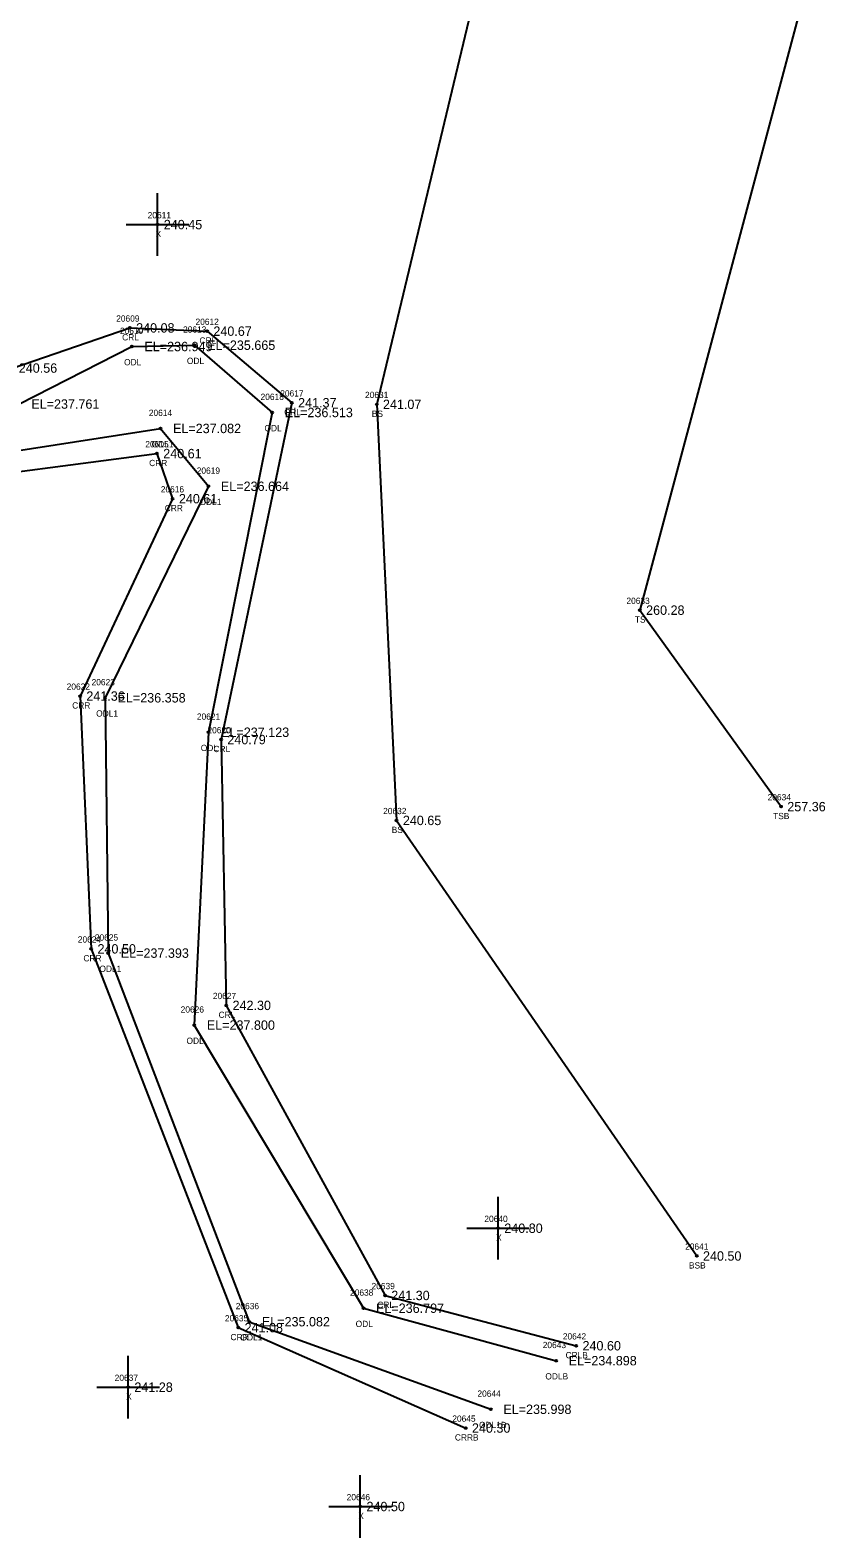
# Model space of a CAD drawing. Extents: x 2275563 to 2277161, y 1075719 to 1076412.
# Drawn here: x 2276442.5 to 2276569.6, y 1075719.3 to 1075959.9 of the extents above; entities that cross this region are included whole.
import ezdxf

# ---------------------------------------------------------------- set-up
doc = ezdxf.new("R2010")
doc.units = 0
for name, color, linetype in [('RD_DTM_BkLn2', 7, 'Continuous'), ('RD_DTM_BkLn_txCode', 7, 'Continuous'), ('RD_EX_H2O', 7, 'Continuous'), ('RD_EX_H2O_txCode', 7, 'Continuous'), ('RD_EX_Misc', 7, 'Continuous'), ('RD_EX_Misc_txCode', 7, 'Continuous'), ('RD_EX_TX_H2O_ELEV', 7, 'Continuous'), ('RD_EX_TX_Misc_ELEV', 7, 'Continuous'), ('RD_SMD_Locator', 7, 'Continuous')]:
    doc.layers.add(name, color=color, linetype=linetype)

msp = doc.modelspace()

# ---------------------------------------------------------------- linework, layer by layer
at = {"layer": 'RD_DTM_BkLn2'}
for points in [[(2276519.11, 1075988.97), (2276497.82, 1075900.18), (2276501, 1075833.77), (2276548.94, 1075764.25)], [(2276569.56, 1075978.62), (2276539.85, 1075867.33), (2276562.4, 1075835.97)]]:
    msp.add_lwpolyline(points, dxfattribs=at)
at = {"layer": 'RD_EX_H2O'}
for points in [[(2276371.99, 1076084.86), (2276373.47, 1076057.63), (2276371.02, 1076053.34), (2276370.27, 1076037.47), (2276373.78, 1076001.78), (2276377.12, 1075939.07), (2276387.12, 1075924.65), (2276409.24, 1075914.33), (2276440.66, 1075900.23), (2276458.72, 1075909.41), (2276468.75, 1075909.62), (2276481.14, 1075898.88), (2276470.97, 1075847.84), (2276468.69, 1075801.1), (2276495.71, 1075755.91), (2276526.48, 1075747.54)], [(2276337.52, 1076082.32), (2276336.19, 1076056.07), (2276339.64, 1076049.32), (2276347.49, 1076019.86), (2276346.94, 1075980.53), (2276334.04, 1075961.68), (2276358.91, 1075924.16), (2276390.72, 1075889.91), (2276404.64, 1075906.32), (2276409.35, 1075902.87), (2276425.82, 1075890.52), (2276463.29, 1075896.33), (2276470.94, 1075887.1), (2276454.43, 1075853.34), (2276454.95, 1075812.59), (2276477.48, 1075753.76), (2276516.05, 1075739.78)], [(2276374.66, 1076053.77), (2276373.09, 1076038.49), (2276378.35, 1076001.85), (2276379.41, 1075939.56), (2276393.18, 1075928.69), (2276410.52, 1075916.05), (2276439.66, 1075905.97), (2276458.4, 1075912.38), (2276470.74, 1075911.86), (2276484.27, 1075900.43), (2276472.97, 1075846.67), (2276473.8, 1075804.25), (2276499.15, 1075757.95), (2276529.69, 1075749.92)], [(2276331.39, 1075956.06), (2276351.04, 1075920.9), (2276389.88, 1075888.34), (2276407.37, 1075900.15), (2276425.36, 1075887.46), (2276462.73, 1075892.32), (2276465.23, 1075885.12), (2276450.45, 1075853.62), (2276452.23, 1075813.27), (2276475.72, 1075752.81), (2276512.04, 1075736.79)]]:
    msp.add_lwpolyline(points, dxfattribs=at)
at = {"layer": 'RD_EX_Misc'}
for p, q in [((2276462.82, 1075923.87), (2276462.82, 1075933.87)), ((2276457.82, 1075928.87), (2276467.82, 1075928.87)), ((2276517.2, 1075763.68), (2276517.2, 1075773.68)), ((2276512.2, 1075768.68), (2276522.2, 1075768.68)), ((2276458.12, 1075738.31), (2276458.12, 1075748.31)), ((2276453.12, 1075743.31), (2276463.12, 1075743.31)), ((2276495.19, 1075719.26), (2276495.19, 1075729.26)), ((2276490.19, 1075724.26), (2276500.19, 1075724.26))]:
    msp.add_line(p, q, dxfattribs=at)
at = {"layer": 'RD_SMD_Locator'}
for centre in [(2276462.82, 1075928.87), (2276458.4, 1075912.38), (2276470.74, 1075911.86), (2276458.72, 1075909.41), (2276468.75, 1075909.62), (2276484.27, 1075900.43), (2276497.82, 1075900.18), (2276481.14, 1075898.88), (2276463.29, 1075896.33), (2276462.73, 1075892.32), (2276470.94, 1075887.1), (2276465.23, 1075885.12), (2276539.85, 1075867.33), (2276450.45, 1075853.62), (2276454.43, 1075853.34), (2276470.97, 1075847.84), (2276472.97, 1075846.67), (2276562.4, 1075835.97), (2276501, 1075833.77), (2276452.23, 1075813.27), (2276454.95, 1075812.59), (2276473.8, 1075804.25), (2276468.69, 1075801.1), (2276517.2, 1075768.68), (2276548.94, 1075764.25), (2276499.15, 1075757.95), (2276495.71, 1075755.91), (2276477.48, 1075753.76), (2276475.72, 1075752.81), (2276529.69, 1075749.92), (2276526.48, 1075747.54), (2276458.12, 1075743.31), (2276516.05, 1075739.78), (2276512.04, 1075736.79), (2276495.19, 1075724.26)]:
    msp.add_circle(centre, 0.15, dxfattribs=at)

# ---------------------------------------------------------------- texts
at = {"layer": 'RD_DTM_BkLn_txCode'}
for s, p in [('20631', (2276495.96, 1075901.18)), ('BS', (2276497.04, 1075898.18)), ('20633', (2276537.71, 1075868.33)), ('TS', (2276539.06, 1075865.33)), ('20634', (2276560.26, 1075836.97)), ('20632', (2276498.85, 1075834.77)), ('TSB', (2276561.13, 1075833.97)), ('BS', (2276500.22, 1075831.77)), ('20641', (2276547.08, 1075765.25)), ('BSB', (2276547.69, 1075762.25))]:
    msp.add_text(s, height=1, dxfattribs=at).set_placement(p)
at = {"layer": 'RD_EX_H2O_txCode'}
for s, p in [('20609', (2276456.22, 1075913.38)), ('20610', (2276456.82, 1075911.41)), ('20613', (2276466.9, 1075911.62)), ('20612', (2276468.89, 1075912.86)), ('CRL', (2276457.17, 1075910.38)), ('CRL', (2276469.52, 1075909.86)), ('ODL', (2276457.48, 1075906.41)), ('ODL', (2276467.51, 1075906.62)), ('20617', (2276482.42, 1075901.43)), ('20618', (2276479.28, 1075900.88)), ('20614', (2276461.43, 1075898.33)), ('CRL', (2276483.05, 1075898.43)), ('ODL', (2276479.9, 1075895.88)), ('20615', (2276460.87, 1075893.32)), ('ODL1', (2276461.88, 1075893.33)), ('CRR', (2276461.48, 1075890.32)), ('20619', (2276469.08, 1075889.1)), ('20616', (2276463.34, 1075886.12)), ('CRR', (2276463.97, 1075883.12)), ('ODL1', (2276469.53, 1075884.1)), ('20622', (2276448.31, 1075854.62)), ('20623', (2276452.29, 1075855.34)), ('CRR', (2276449.19, 1075851.62)), ('ODL1', (2276453.02, 1075850.34)), ('20621', (2276469.11, 1075849.84)), ('20620', (2276470.79, 1075847.67)), ('ODL', (2276469.73, 1075844.84)), ('CRL', (2276471.75, 1075844.67)), ('20625', (2276452.81, 1075814.59)), ('20624', (2276450.09, 1075814.27)), ('CRR', (2276450.98, 1075811.27)), ('ODL1', (2276453.54, 1075809.59)), ('20627', (2276471.66, 1075805.25)), ('20626', (2276466.52, 1075803.1)), ('CRL', (2276472.57, 1075802.25)), ('ODL', (2276467.45, 1075798.1)), ('20638', (2276493.57, 1075757.91)), ('20639', (2276497, 1075758.95)), ('20636', (2276475.31, 1075755.76)), ('CRL', (2276497.92, 1075755.95)), ('20635', (2276473.58, 1075753.81)), ('ODL', (2276494.46, 1075752.91)), ('CRR', (2276474.47, 1075750.81)), ('ODL1', (2276476.07, 1075750.76)), ('20642', (2276527.55, 1075750.92)), ('20643', (2276524.34, 1075749.54)), ('CRLB', (2276527.99, 1075747.92)), ('ODLB', (2276524.76, 1075744.54)), ('20644', (2276513.91, 1075741.78)), ('20645', (2276509.9, 1075737.79)), ('ODL1B', (2276514.17, 1075736.78)), ('CRRB', (2276510.31, 1075734.79))]:
    msp.add_text(s, height=1, dxfattribs=at).set_placement(p)
at = {"layer": 'RD_EX_Misc_txCode'}
for s, p in [('20611', (2276461.25, 1075929.87)), ('X', (2276462.51, 1075926.87)), ('20640', (2276515.02, 1075769.68)), ('X', (2276516.89, 1075766.68)), ('20637', (2276455.98, 1075744.31)), ('X', (2276457.81, 1075741.31)), ('20646', (2276493.03, 1075725.26)), ('X', (2276494.88, 1075722.26))]:
    msp.add_text(s, height=1, dxfattribs=at).set_placement(p)
at = {"layer": 'RD_EX_TX_H2O_ELEV'}
for s, p in [('240.08', (2276459.4, 1075911.63)), ('240.67', (2276471.74, 1075911.11)), ('EL=236.949', (2276460.72, 1075908.66)), ('EL=235.665', (2276470.75, 1075908.87)), ('240.56', (2276440.66, 1075905.22)), ('EL=237.761', (2276442.66, 1075899.48)), ('241.37', (2276485.27, 1075899.68)), ('EL=236.513', (2276483.14, 1075898.13)), ('EL=237.082', (2276465.29, 1075895.58)), ('240.61', (2276463.73, 1075891.57)), ('EL=236.664', (2276472.94, 1075886.35)), ('240.61', (2276466.23, 1075884.37)), ('241.36', (2276451.45, 1075852.87)), ('EL=236.358', (2276456.43, 1075852.59)), ('EL=237.123', (2276472.97, 1075847.09)), ('240.79', (2276473.97, 1075845.92)), ('240.50', (2276453.23, 1075812.52)), ('EL=237.393', (2276456.95, 1075811.84)), ('242.30', (2276474.8, 1075803.5)), ('EL=237.800', (2276470.69, 1075800.35)), ('241.30', (2276500.15, 1075757.2)), ('EL=236.797', (2276497.71, 1075755.16)), ('241.08', (2276476.72, 1075752.06)), ('EL=235.082', (2276479.48, 1075753.01)), ('240.60', (2276530.69, 1075749.17)), ('EL=234.898', (2276528.48, 1075746.79)), ('EL=235.998', (2276518.05, 1075739.03)), ('240.30', (2276513.04, 1075736.04))]:
    msp.add_text(s, height=1.5, dxfattribs=at).set_placement(p)
at = {"layer": 'RD_EX_TX_Misc_ELEV'}
for s, p in [('240.45', (2276463.82, 1075928.12)), ('241.07', (2276498.82, 1075899.43)), ('260.28', (2276540.85, 1075866.58)), ('257.36', (2276563.4, 1075835.22)), ('240.65', (2276502, 1075833.02)), ('240.80', (2276518.2, 1075767.93)), ('240.50', (2276549.94, 1075763.5)), ('241.28', (2276459.12, 1075742.56)), ('240.50', (2276496.19, 1075723.51))]:
    msp.add_text(s, height=1.5, dxfattribs=at).set_placement(p)

doc.saveas('drawing.dxf')
